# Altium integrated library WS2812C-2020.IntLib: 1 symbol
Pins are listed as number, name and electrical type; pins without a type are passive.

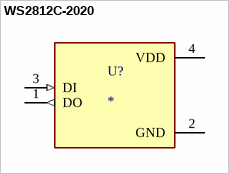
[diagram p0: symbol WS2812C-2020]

## WS2812C-2020
designator U?
Intelligent control LED integrated light source; MF: Worldsemi; MP: WS2812C-2020
footprint LED_WS2812C-2020
pins: 1 DO (out), 2 GND (power), 3 DI (in), 4 VDD (power)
